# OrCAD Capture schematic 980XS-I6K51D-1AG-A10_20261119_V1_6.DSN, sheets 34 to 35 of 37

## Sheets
34 P0042_S4_USB/AUD/FLASH/XTAL: size A1
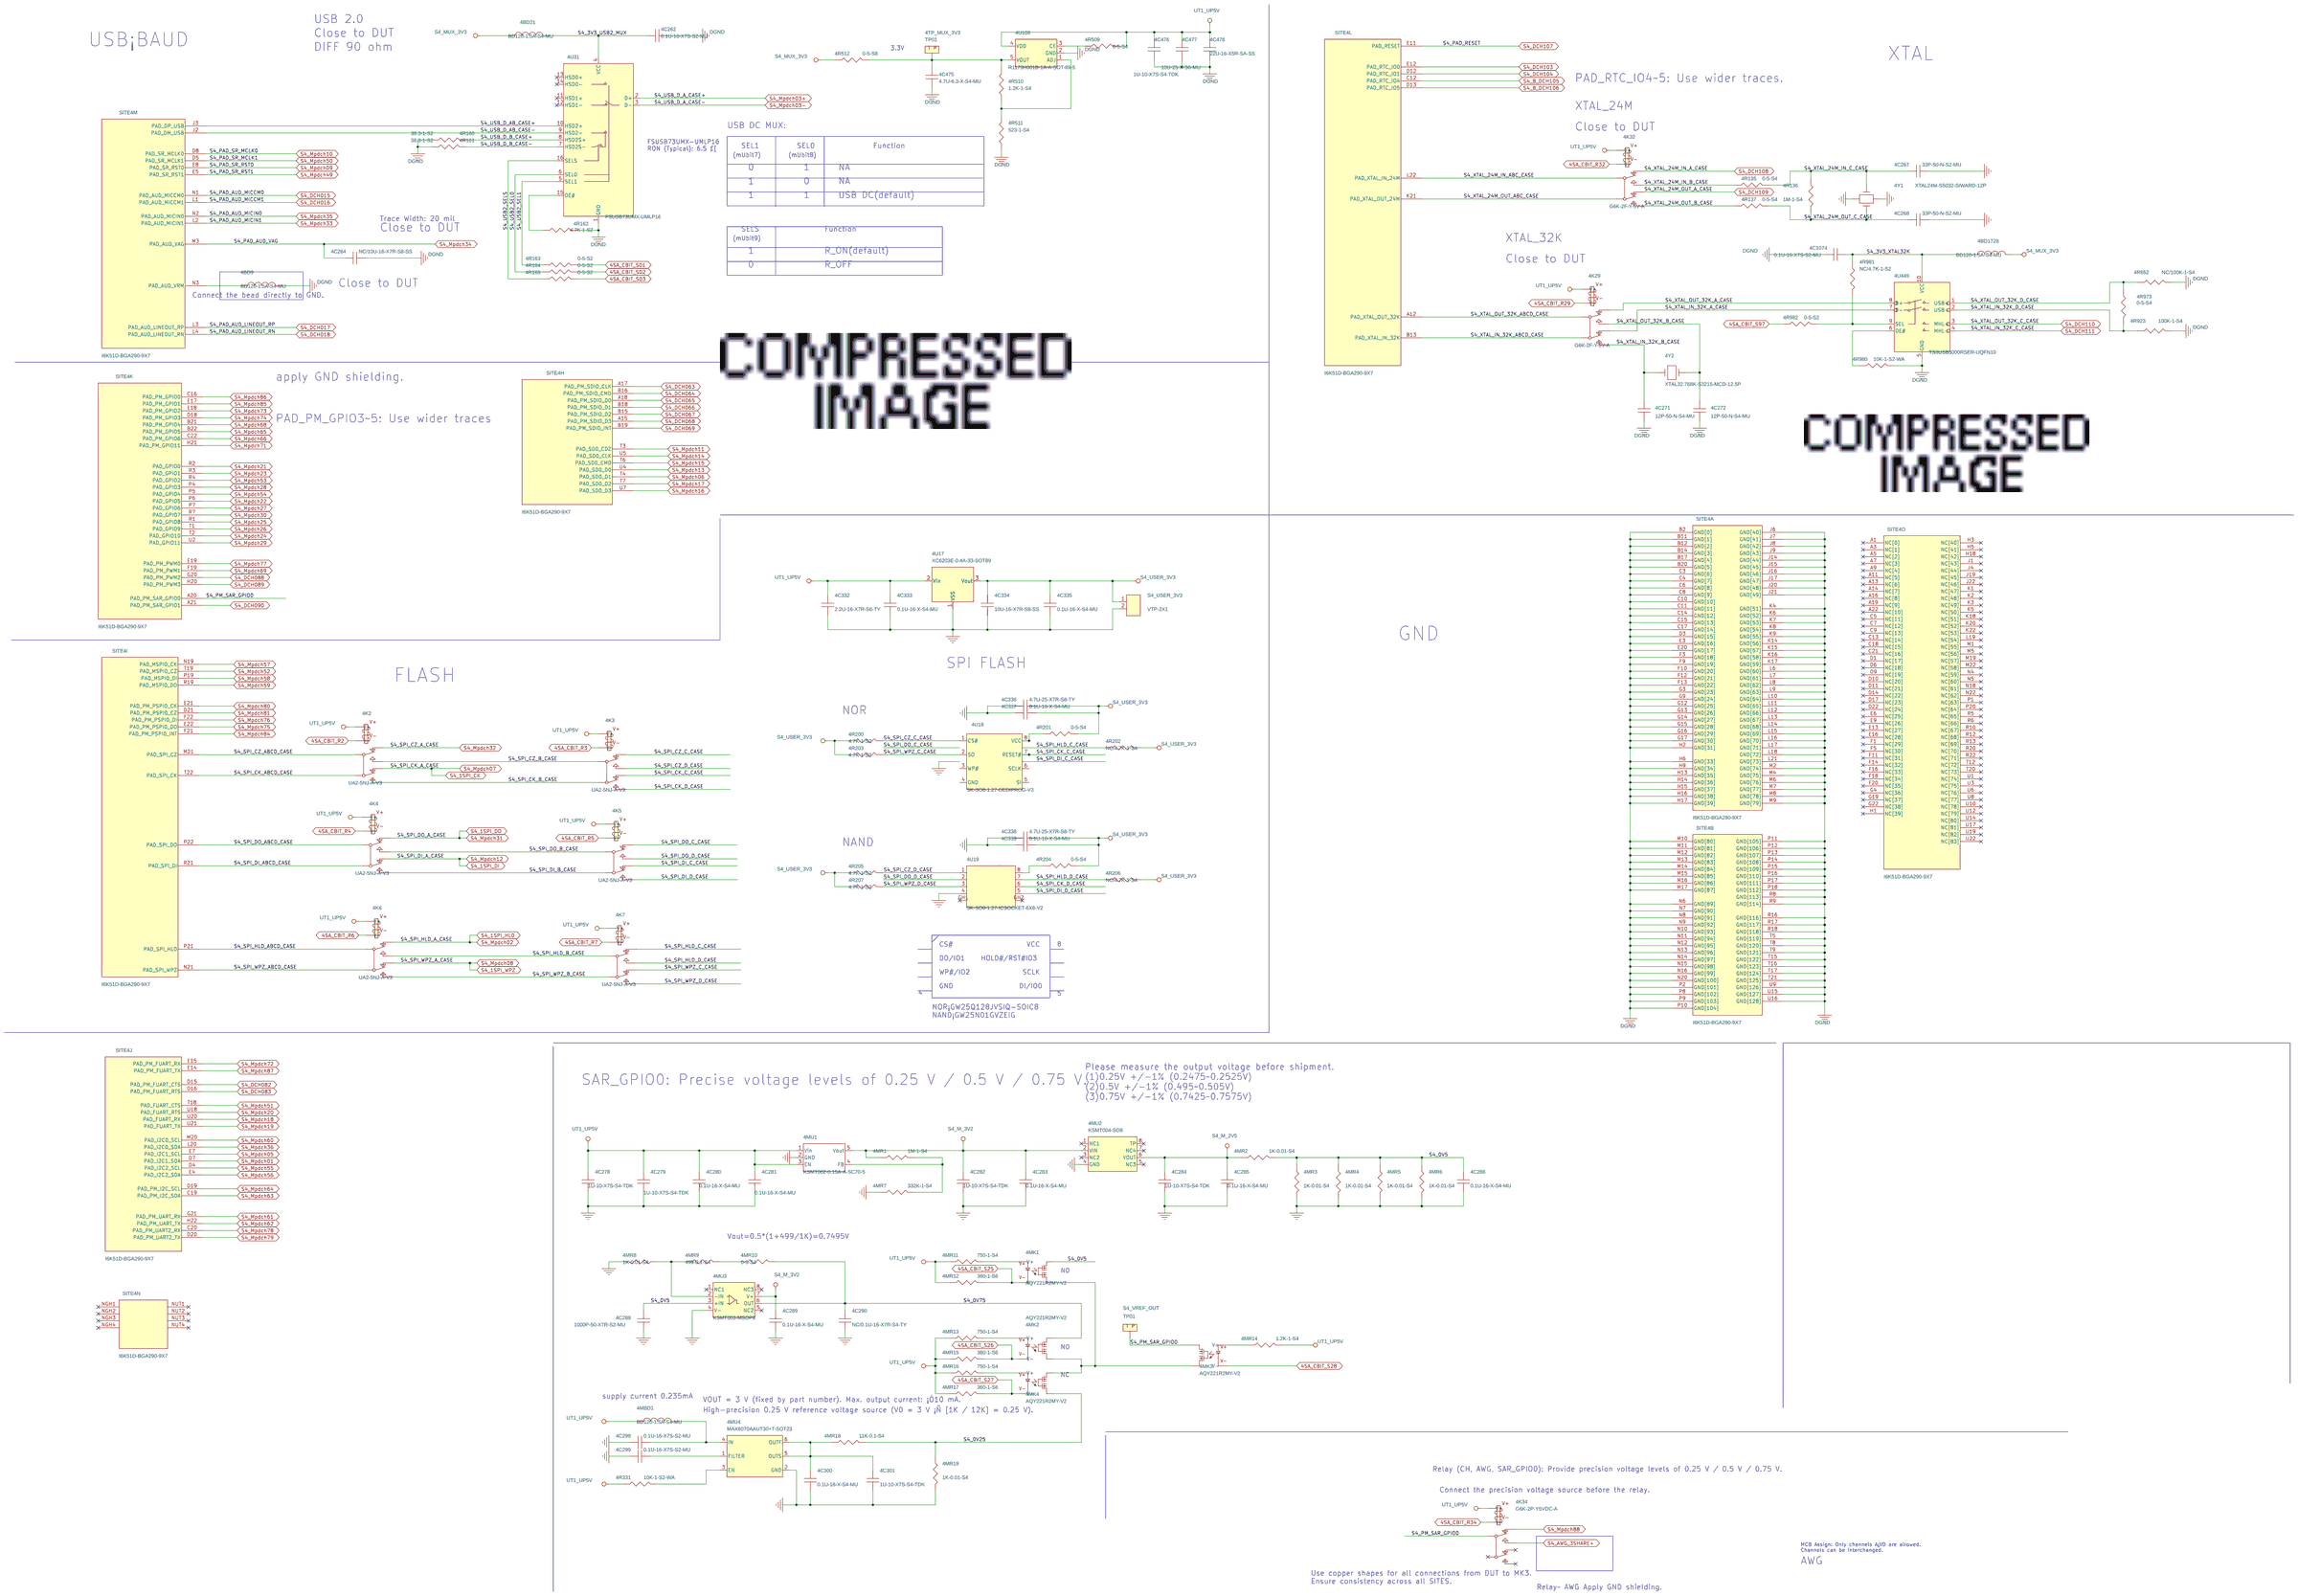
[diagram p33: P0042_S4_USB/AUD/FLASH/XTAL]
35 P0072_S7_USB/AUD/FLASH/XTAL: size A1
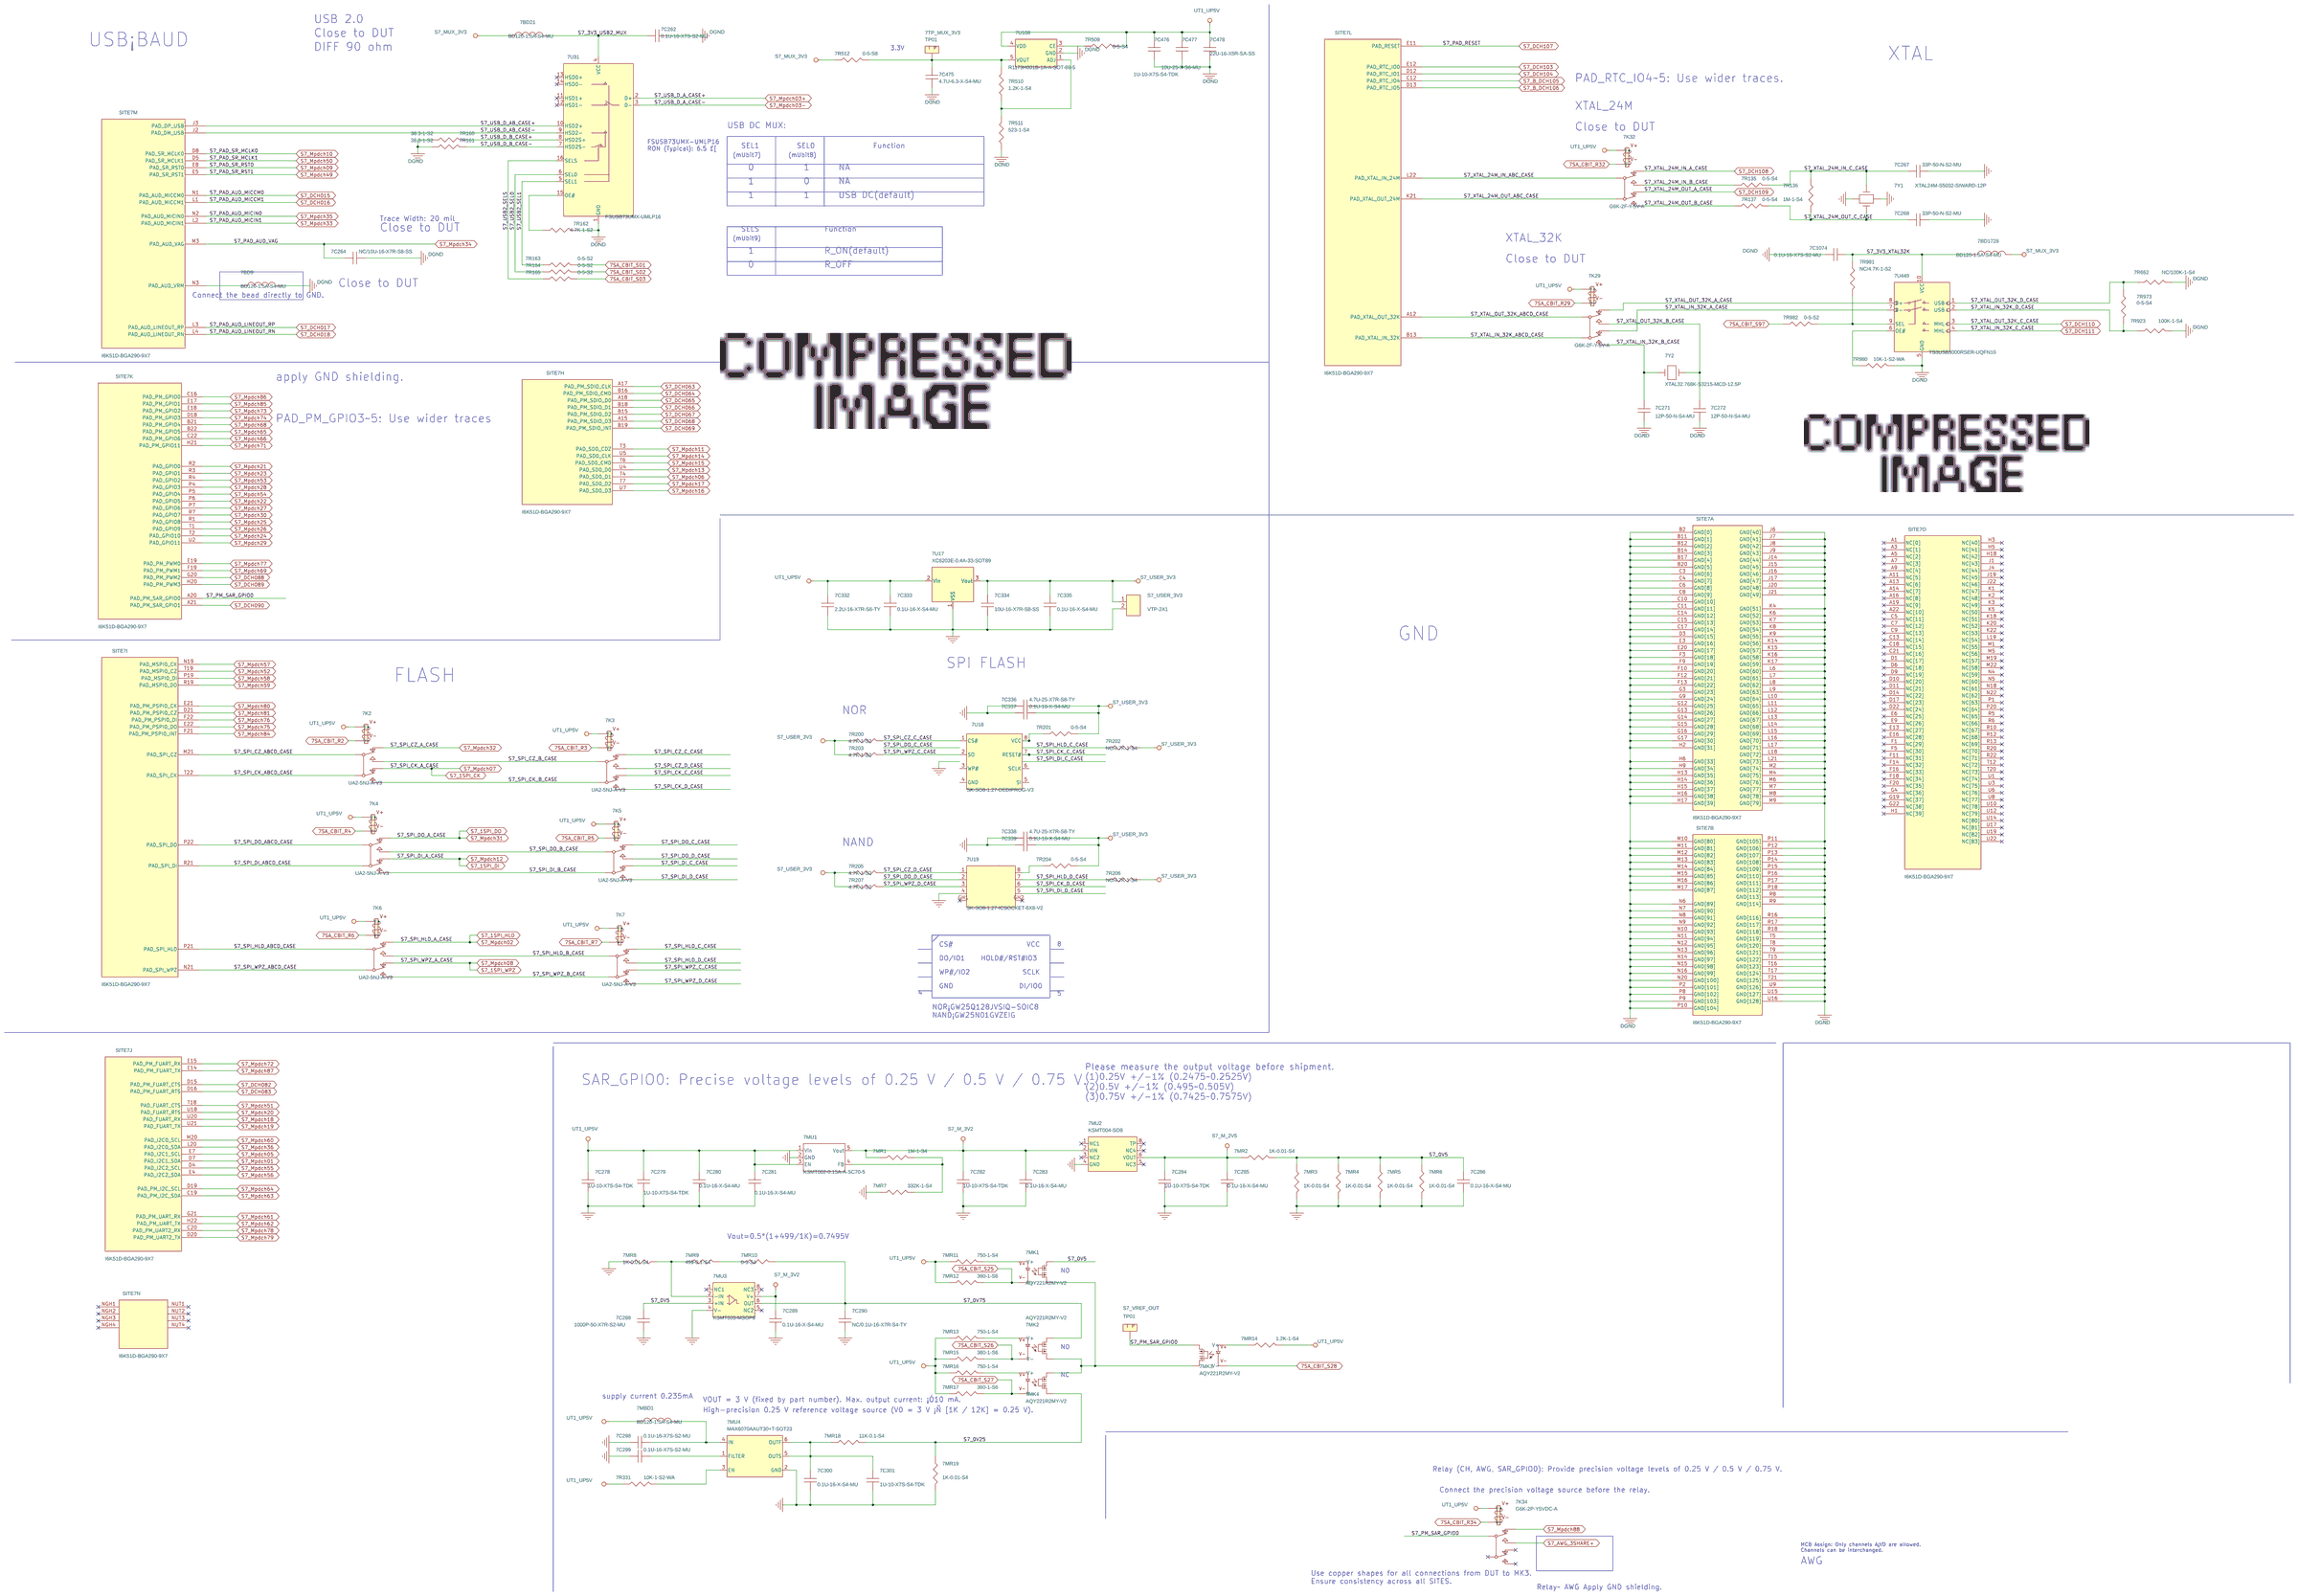
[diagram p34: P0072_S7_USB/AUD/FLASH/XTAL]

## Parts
sheet P0041_S4_POWER
SITE4  I6K51D-BGA290-9X7  [SK_TFBGA7X9_290P_0P4MM_JG]  (sections A,B,C,D,E,F,G,H,I,J,K,L,M,N,O)
sheet P0042_S4_USB/AUD/FLASH/XTAL
4BD9  BD120-1.5A-S4-MU  [FB0402]
4BD21  BD120-1.5A-S4-MU  [FB0402]
4BD1728  BD120-1.5A-S4-MU  [FB0402]
4C262  0.1U-16-X7S-S2-MU  [C0201]
4C264  NC/10U-16-X7R-S8-SS  [C0805]
4C267  33P-50-N-S2-MU  [C0201]
4C268  33P-50-N-S2-MU  [C0201]
4C271  12P-50-N-S4-MU  [C0402]
4C272  12P-50-N-S4-MU  [C0402]
4C278  1U-10-X7S-S4-TDK  [C0402]
4C279  1U-10-X7S-S4-TDK  [C0402]
4C280  0.1U-16-X-S4-MU  [C0402]
4C281  0.1U-16-X-S4-MU  [C0402]
4C282  1U-10-X7S-S4-TDK  [C0402]
4C283  0.1U-16-X-S4-MU  [C0402]
4C284  1U-10-X7S-S4-TDK  [C0402]
4C285  0.1U-16-X-S4-MU  [C0402]
4C286  0.1U-16-X-S4-MU  [C0402]
4C288  1000P-50-X7R-S2-MU  [C0201]
4C289  0.1U-16-X-S4-MU  [C0402]
4C290  NC/0.1U-16-X7R-S4-TY  [C0402]
4C298  0.1U-16-X7S-S2-MU  [C0201]
4C299  0.1U-16-X7S-S2-MU  [C0201]
4C300  0.1U-16-X-S4-MU  [C0402]
4C301  1U-10-X7S-S4-TDK  [C0402]
4C332  2.2U-16-X7R-S6-TY  [C0603]
4C333  0.1U-16-X-S4-MU  [C0402]
4C334  10U-16-X7R-S8-SS  [C0805]
4C335  0.1U-16-X-S4-MU  [C0402]
4C336  4.7U-25-X7R-S8-TY  [C0805]
4C337  0.1U-16-X-S4-MU  [C0402]
4C338  4.7U-25-X7R-S8-TY  [C0805]
4C339  0.1U-16-X-S4-MU  [C0402]
4C475  4.7U-6.3-X-S4-MU  [C0402]
4C476  1U-10-X7S-S4-TDK  [C0402]
4C477  10U-25-X-S6-MU  [C0603]
4C478  22U-16-X5R-SA-SS  [C1206]
4C1074  0.1U-16-X7S-S2-MU  [C0201_MINI]
4K2  UA2-5NJ-A-V3  [RL_NECUA2_5V_V3]
4K3  UA2-5NJ-A-V3  [RL_NECUA2_5V_V3]
4K4  UA2-5NJ-A-V3  [RL_NECUA2_5V_V3]
4K5  UA2-5NJ-A-V3  [RL_NECUA2_5V_V3]
4K6  UA2-5NJ-A-V3  [RL_NECUA2_5V_V3]
4K7  UA2-5NJ-A-V3  [RL_NECUA2_5V_V3]
4K29  G6K-2F-Y-5V-A  [RL_G6K2F-Y_5V_OMRON]
4K32  G6K-2F-Y-5V-A  [RL_G6K2F-Y_5V_OMRON]
4K34  G6K-2P-Y5VDC-A  [RL_OMRONG6K2PY_5V]
4MBD1  BD120-1.5A-S4-MU  [FB0402]
4MK1  AQY221R2MY-V2  [RL_AQY221R2MY_5V_V2]
4MK2  AQY221R2MY-V2  [RL_AQY221R2MY_5V_V2]
4MK3  AQY221R2MY-V2  [RL_AQY221R2MY_5V_V2]
4MK4  AQY221R2MY-V2  [RL_AQY221R2MY_5V_V2]
4MR1  1M-1-S4  [R0402_UNBGA_V2]
4MR2  1K-0.01-S4  [R0402_UNBGA_V2]
4MR3  1K-0.01-S4  [R0402_UNBGA_V2]
4MR4  1K-0.01-S4  [R0402_UNBGA_V2]
4MR5  1K-0.01-S4  [R0402_UNBGA_V2]
4MR6  1K-0.01-S4  [R0402_UNBGA_V2]
4MR7  332K-1-S4  [R0402_UNBGA_V2]
4MR8  1K-0.01-S4  [R0402_UNBGA_V2]
4MR9  499-0.1-S4  [R0402]
4MR10  0-5-S4  [R0402]
4MR11  750-1-S4  [R0402]
4MR12  360-1-S6  [R0603]
4MR13  750-1-S4  [R0402]
4MR14  1.2K-1-S4  [R0402]
4MR15  360-1-S6  [R0603]
4MR16  750-1-S4  [R0402]
4MR17  360-1-S6  [R0603]
4MR18  11K-0.1-S4  [R0402]
4MR19  1K-0.01-S4  [R0402_UNBGA_V2]
4MU1  KSMT002-0.15A-A-SC70-5  [SC70_5P]
4MU2  KSMT004-SO8  [SO8_244X127MM]
4MU3  KSMT003-MSOP8  [SO8_172X0P65MM]
4MU4  MAX6070AAUT30+T-SOT23  [SOT23_6P_0P95X2P7MM_H1P45MM]
4R135  0-5-S4  [R0402]
4R136  1M-1-S4  [R0402]
4R137  0-5-S4  [R0402]
4R160  38.3-1-S2  [R0201_MINI]
4R161  38.3-1-S2  [R0201_MINI]
4R162  4.7K-1-S2  [R0201_MINI]
4R163  0-5-S2  [R0201_MINI]
4R164  0-5-S2  [R0201_MINI]
4R165  0-5-S2  [R0201_MINI]
4R200  4.7K-1-S2  [R0201]
4R201  0-5-S4  [R0402]
4R202  NC/4.7K-1-S4  [R0402]
4R203  4.7K-1-S2  [R0201]
4R204  0-5-S4  [R0402]
4R205  4.7K-1-S2  [R0201]
4R206  NC/4.7K-1-S4  [R0402]
4R207  4.7K-1-S2  [R0201]
4R331  10K-1-S2-WA  [R0201]
4R509  0-5-S4  [R0402]
4R510  1.2K-1-S4  [R0402]
4R511  523-1-S4  [R0402]
4R512  0-5-S8  [R0805]
4R652  NC/100K-1-S4  [R0402]
4R923  100K-1-S4  [R0402]
4R973  0-5-S4  [R0402]
4R980  10K-1-S2-WA  [R0201]
4R981  NC/4.7K-1-S2  [R0201]
4R982  0-5-S2  [R0201]
4TP_MUX_3V3  TP01  [TP_040_T]
4U17  XC6203E-0.4A-33-SOT89  [SOT89]
4U18  SK-SO8-1.27-DEDIPROG-V3  [SK_SO8_1P27MM_DEDIPROG_V3]
4U19  SK-SO8-1.27-ICSOCKET-6X8-V2  [SK_SO8_1P27MM_SDQ54CBAA_V2]
4U31  FSUSB73UMX-UMLP16  [SW_UMLP2P6X1P8_12P_0P4MM]
4U108  R1173H001B-1A-A-SOT-89-5  [SOT_89_5]
4U449  TS3USB3000RSER-UQFN10  [UQFN2P05X1P55_10P_0P5MM]
4Y1  XTAL24M-S5032-SIWARD-12P  [XTAL_S_DUAL1]
4Y2  XTAL32.768K-S3215-MCD-12.5P  [XTAL_3P2X1P5MM_2P_MC]
S4_USER_3V3  VTP-2X1  [VTP_2P_100]
S4_VREF_OUT  TP01  [TP_040_T]
sheet P0072_S7_USB/AUD/FLASH/XTAL
7BD9  BD120-1.5A-S4-MU  [FB0402]
7BD21  BD120-1.5A-S4-MU  [FB0402]
7BD1728  BD120-1.5A-S4-MU  [FB0402]
7C262  0.1U-16-X7S-S2-MU  [C0201]
7C264  NC/10U-16-X7R-S8-SS  [C0805]
7C267  33P-50-N-S2-MU  [C0201]
7C268  33P-50-N-S2-MU  [C0201]
7C271  12P-50-N-S4-MU  [C0402]
7C272  12P-50-N-S4-MU  [C0402]
7C278  1U-10-X7S-S4-TDK  [C0402]
7C279  1U-10-X7S-S4-TDK  [C0402]
7C280  0.1U-16-X-S4-MU  [C0402]
7C281  0.1U-16-X-S4-MU  [C0402]
7C282  1U-10-X7S-S4-TDK  [C0402]
7C283  0.1U-16-X-S4-MU  [C0402]
7C284  1U-10-X7S-S4-TDK  [C0402]
7C285  0.1U-16-X-S4-MU  [C0402]
7C286  0.1U-16-X-S4-MU  [C0402]
7C288  1000P-50-X7R-S2-MU  [C0201]
7C289  0.1U-16-X-S4-MU  [C0402]
7C290  NC/0.1U-16-X7R-S4-TY  [C0402]
7C298  0.1U-16-X7S-S2-MU  [C0201]
7C299  0.1U-16-X7S-S2-MU  [C0201]
7C300  0.1U-16-X-S4-MU  [C0402]
7C301  1U-10-X7S-S4-TDK  [C0402]
7C332  2.2U-16-X7R-S6-TY  [C0603]
7C333  0.1U-16-X-S4-MU  [C0402]
7C334  10U-16-X7R-S8-SS  [C0805]
7C335  0.1U-16-X-S4-MU  [C0402]
7C336  4.7U-25-X7R-S8-TY  [C0805]
7C337  0.1U-16-X-S4-MU  [C0402]
7C338  4.7U-25-X7R-S8-TY  [C0805]
7C339  0.1U-16-X-S4-MU  [C0402]
7C475  4.7U-6.3-X-S4-MU  [C0402]
7C476  1U-10-X7S-S4-TDK  [C0402]
7C477  10U-25-X-S6-MU  [C0603]
7C478  22U-16-X5R-SA-SS  [C1206]
7C1074  0.1U-16-X7S-S2-MU  [C0201_MINI]
7K2  UA2-5NJ-A-V3  [RL_NECUA2_5V_V3]
7K3  UA2-5NJ-A-V3  [RL_NECUA2_5V_V3]
7K4  UA2-5NJ-A-V3  [RL_NECUA2_5V_V3]
7K5  UA2-5NJ-A-V3  [RL_NECUA2_5V_V3]
7K6  UA2-5NJ-A-V3  [RL_NECUA2_5V_V3]
7K7  UA2-5NJ-A-V3  [RL_NECUA2_5V_V3]
7K29  G6K-2F-Y-5V-A  [RL_G6K2F-Y_5V_OMRON]
7K32  G6K-2F-Y-5V-A  [RL_G6K2F-Y_5V_OMRON]
7K34  G6K-2P-Y5VDC-A  [RL_OMRONG6K2PY_5V]
7MBD1  BD120-1.5A-S4-MU  [FB0402]
7MK1  AQY221R2MY-V2  [RL_AQY221R2MY_5V_V2]
7MK2  AQY221R2MY-V2  [RL_AQY221R2MY_5V_V2]
7MK3  AQY221R2MY-V2  [RL_AQY221R2MY_5V_V2]
7MK4  AQY221R2MY-V2  [RL_AQY221R2MY_5V_V2]
7MR1  1M-1-S4  [R0402_UNBGA_V2]
7MR2  1K-0.01-S4  [R0402_UNBGA_V2]
7MR3  1K-0.01-S4  [R0402_UNBGA_V2]
7MR4  1K-0.01-S4  [R0402_UNBGA_V2]
7MR5  1K-0.01-S4  [R0402_UNBGA_V2]
7MR6  1K-0.01-S4  [R0402_UNBGA_V2]
7MR7  332K-1-S4  [R0402_UNBGA_V2]
7MR8  1K-0.01-S4  [R0402_UNBGA_V2]
7MR9  499-0.1-S4  [R0402]
7MR10  0-5-S4  [R0402]
7MR11  750-1-S4  [R0402]
7MR12  360-1-S6  [R0603]
7MR13  750-1-S4  [R0402]
7MR14  1.2K-1-S4  [R0402]
7MR15  360-1-S6  [R0603]
7MR16  750-1-S4  [R0402]
7MR17  360-1-S6  [R0603]
7MR18  11K-0.1-S4  [R0402]
7MR19  1K-0.01-S4  [R0402_UNBGA_V2]
7MU1  KSMT002-0.15A-A-SC70-5  [SC70_5P]
7MU2  KSMT004-SO8  [SO8_244X127MM]
7MU3  KSMT003-MSOP8  [SO8_172X0P65MM]
7MU4  MAX6070AAUT30+T-SOT23  [SOT23_6P_0P95X2P7MM_H1P45MM]
7R135  0-5-S4  [R0402]
7R136  1M-1-S4  [R0402]
7R137  0-5-S4  [R0402]
7R160  38.3-1-S2  [R0201_MINI]
7R161  38.3-1-S2  [R0201_MINI]
7R162  4.7K-1-S2  [R0201_MINI]
7R163  0-5-S2  [R0201_MINI]
7R164  0-5-S2  [R0201_MINI]
7R165  0-5-S2  [R0201_MINI]
7R200  4.7K-1-S2  [R0201]
7R201  0-5-S4  [R0402]
7R202  NC/4.7K-1-S4  [R0402]
7R203  4.7K-1-S2  [R0201]
7R204  0-5-S4  [R0402]
7R205  4.7K-1-S2  [R0201]
7R206  NC/4.7K-1-S4  [R0402]
7R207  4.7K-1-S2  [R0201]
7R331  10K-1-S2-WA  [R0201]
7R509  0-5-S4  [R0402]
7R510  1.2K-1-S4  [R0402]
7R511  523-1-S4  [R0402]
7R512  0-5-S8  [R0805]
7R652  NC/100K-1-S4  [R0402]
7R923  100K-1-S4  [R0402]
7R973  0-5-S4  [R0402]
7R980  10K-1-S2-WA  [R0201]
7R981  NC/4.7K-1-S2  [R0201]
7R982  0-5-S2  [R0201]
7TP_MUX_3V3  TP01  [TP_040_T]
7U17  XC6203E-0.4A-33-SOT89  [SOT89]
7U18  SK-SO8-1.27-DEDIPROG-V3  [SK_SO8_1P27MM_DEDIPROG_V3]
7U19  SK-SO8-1.27-ICSOCKET-6X8-V2  [SK_SO8_1P27MM_SDQ54CBAA_V2]
7U31  FSUSB73UMX-UMLP16  [SW_UMLP2P6X1P8_12P_0P4MM]
7U108  R1173H001B-1A-A-SOT-89-5  [SOT_89_5]
7U449  TS3USB3000RSER-UQFN10  [UQFN2P05X1P55_10P_0P5MM]
7Y1  XTAL24M-S5032-SIWARD-12P  [XTAL_S_DUAL1]
7Y2  XTAL32.768K-S3215-MCD-12.5P  [XTAL_3P2X1P5MM_2P_MC]
S7_USER_3V3  VTP-2X1  [VTP_2P_100]
S7_VREF_OUT  TP01  [TP_040_T]
SITE7  I6K51D-BGA290-9X7  [SK_TFBGA7X9_290P_0P4MM_JG]  (sections A,B,C,D,E,F,G,H,I,J,K,L,M,N,O)

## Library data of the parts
SITE4 SITE7 = I6K51D-BGA290-9X7
4BD9 7BD9 = BD120-1.5A-S4-MU: KAIROSNAME: BD9
4BD21 4BD1728 7BD21 7BD1728 = BD120-1.5A-S4-MU: KAIROSNAME: BD21
4C262 7C262 = 0.1U-16-X7S-S2-MU
4C264 7C264 = 10U-16-X7R-S8-SS: KAIROSNAME: C264
4C267 7C267 = 33P-50-N-S2-MU: KAIROSNAME: C267
4C268 7C268 = 33P-50-N-S2-MU: KAIROSNAME: C268
4C271 7C271 = 12P-50-N-S4-MU: KAIROSNAME: C271
4C272 7C272 = 12P-50-N-S4-MU: KAIROSNAME: C272
4C278 7C278 = 1U-10-X7S-S4-TDK: KAIROSNAME: C278
4C279 7C279 = 1U-10-X7S-S4-TDK: KAIROSNAME: C279
4C280 7C280 = 0.1U-16-X-S4-MU: KAIROSNAME: C280
4C281 7C281 = 0.1U-16-X-S4-MU: KAIROSNAME: C281
4C282 7C282 = 1U-10-X7S-S4-TDK: KAIROSNAME: C282
4C283 7C283 = 0.1U-16-X-S4-MU: KAIROSNAME: C283
4C284 7C284 = 1U-10-X7S-S4-TDK: KAIROSNAME: C284
4C285 7C285 = 0.1U-16-X-S4-MU: KAIROSNAME: C285
4C286 7C286 = 0.1U-16-X-S4-MU: KAIROSNAME: C286
4C288 7C288 = 1000P-50-X7R-S2-MU: KAIROSNAME: C288
4C289 7C289 = 0.1U-16-X-S4-MU: KAIROSNAME: C289
4C290 7C290 = 0.1U-16-X-S4-MU: KAIROSNAME: C290
4C298 7C298 = 0.1U-16-X7S-S2-MU: KAIROSNAME: C298
4C299 7C299 = 0.1U-16-X7S-S2-MU: KAIROSNAME: C299
4C300 7C300 = 0.1U-16-X-S4-MU: KAIROSNAME: C300
4C301 7C301 = 1U-10-X7S-S4-TDK: KAIROSNAME: C301
4C332 7C332 = 2.2U-16-X7R-S6-TY
4C333 4C335 4C337 4C339 7C333 7C335 7C337 7C339 = 0.1U-16-X-S4-MU
4C334 7C334 = 10U-16-X7R-S8-SS
4C336 4C338 7C336 7C338 = 4.7U-25-X7R-S8-TY
4C475 7C475 = 4.7U-6.3-X-S4-MU: KAIROSNAME: C475
4C476 7C476 = 1U-10-X-S4-MU: KAIROSNAME: C476
4C477 7C477 = 10U-25-X-S6-MU: KAIROSNAME: C477
4C478 7C478 = 22U-16-X5R-SA-SS: KAIROSNAME: C478
4C1074 7C1074 = 0.1U-16-X7S-S2-MU: KAIROSNAME: C262
4K2-4K7 7K2-7K7 = UA2-5NJ-A-V3
4K29 7K29 = G6K-2F-Y-5V-A: KAIROSNAME: K29
4K32 7K32 = G6K-2F-Y-5V-A: KAIROSNAME: K32
4K34 7K34 = G6K-2P-Y5VDC-A: KAIROSNAME: K34
4MBD1 7MBD1 = BD120-1.5A-S4-MU: KAIROSNAME: MBD1
4MK1 7MK1 = AQY221R2MY-V2: KAIROSNAME: MK1
4MK2 7MK2 = AQY221R2MY-V2: KAIROSNAME: MK2
4MK3 7MK3 = AQY221R2MY-V2: KAIROSNAME: MK3
4MK4 7MK4 = AQY221R2MY-V2: KAIROSNAME: MK4
4MR1 7MR1 = 1M-1-S4: KAIROSNAME: MR1
4MR2 7MR2 = 1K-0.01-S4: KAIROSNAME: MR2
4MR3 7MR3 = 1K-0.01-S4: KAIROSNAME: MR3
4MR4 7MR4 = 1K-0.01-S4: KAIROSNAME: MR4
4MR5 7MR5 = 1K-0.01-S4: KAIROSNAME: MR5
4MR6 7MR6 = 1K-0.01-S4: KAIROSNAME: MR6
4MR7 7MR7 = 332K-1-S4: KAIROSNAME: MR7
4MR8 7MR8 = 1K-0.01-S4: KAIROSNAME: MR8
4MR9 7MR9 = 499-0.1-S4: KAIROSNAME: MR9
4MR10 7MR10 = 0-5-S4: KAIROSNAME: MR10
4MR11 7MR11 = 750-1-S4: KAIROSNAME: MR11
4MR12 7MR12 = 360-1-S4: KAIROSNAME: MR12
4MR13 7MR13 = 750-1-S4: KAIROSNAME: MR13
4MR14 7MR14 = 1.2K-1-S4: KAIROSNAME: MR14
4MR15 7MR15 = 360-1-S4: KAIROSNAME: MR15
4MR16 7MR16 = 750-1-S4: KAIROSNAME: MR16
4MR17 7MR17 = 360-1-S4: KAIROSNAME: MR17
4MR18 7MR18 = 11K-0.1-S4: KAIROSNAME: MR18
4MR19 7MR19 = 1K-0.01-S4: KAIROSNAME: MR19
4MU1 7MU1 = KSMT002-0.15A-A-SC70-5: KAIROSNAME: MU1
4MU2 7MU2 = KSMT004-SO8: KAIROSNAME: MU2
4MU3 7MU3 = KSMT003-MSOP8: KAIROSNAME: MU3
4MU4 7MU4 = MAX6070AAUT30+T-SOT23: KAIROSNAME: MU4
4R135 7R135 = 0-5-S4: KAIROSNAME: R135
4R136 7R136 = 1M-1-S4: KAIROSNAME: R136
4R137 7R137 = 0-5-S4: KAIROSNAME: R137
4R160 7R160 = 38.3-1-S2: KAIROSNAME: R160
4R161 7R161 = 38.3-1-S2: KAIROSNAME: R161
4R162 7R162 = 4.7K-1-S2: KAIROSNAME: R162
4R163 7R163 = 0-5-S2: KAIROSNAME: R163
4R164 7R164 = 0-5-S2: KAIROSNAME: R164
4R165 7R165 = 0-5-S2: KAIROSNAME: R165
4R200 4R202 4R203 4R205-4R207 4R981 7R200 7R202 7R203 7R205-7R207 7R981 = 4.7K-1-S2
4R201 4R204 4R973 7R201 7R204 7R973 = 0-5-S4
4R331 7R331 = 10K-1-S2-WA: KAIROSNAME: R331
4R509 7R509 = 0-5-S4: KAIROSNAME: R509
4R510 7R510 = 1.2K-1-S4: KAIROSNAME: R510
4R511 7R511 = 523-1-S4: KAIROSNAME: R511
4R512 7R512 = 0-5-S8: KAIROSNAME: R512
4R652 4R923 7R652 7R923 = 100K-1-S4
4R980 7R980 = 10K-1-S2-WA
4R982 7R982 = 0-5-S2
4TP_MUX_3V3 7TP_MUX_3V3 = TP03-D: KAIROSNAME: TP_MUX_3V3
4U17 7U17 = XC6203E-0.4A-33-SOT89
4U18 7U18 = SK-SO8-1.27-DEDIPROG-V3
4U19 7U19 = SK-SO8-1.27-ICSOCKET-6X8-V2
4U31 7U31 = FSUSB73UMX-UMLP16: KAIROSNAME: U31
4U108 7U108 = R1173H001B-1A-A-SOT-89-5: KAIROSNAME: U108
4U449 7U449 = TS3USB3000RSER-UQFN10
4Y1 7Y1 = XTAL24M-S5032-SIWARD-12P: KAIROSNAME: Y1
4Y2 7Y2 = XTAL32.768K-S3215-MCD-12.5P: KAIROSNAME: Y2
S4_USER_3V3 S7_USER_3V3 = VTP-2X1
S4_VREF_OUT S7_VREF_OUT = TP01: KAIROSNAME: S1_VREF_OUT

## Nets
DGND: 4BD9.2 4C262.2 4C264.2 4C267.2 4C268.2 4C271.2 4C272.2 4C278.2 4C279.2 4C280.2 4C281.2 4C282.2 4C283.2 4C284.2 4C285.2 4C286.2 4C288.2 4C289.2 4C290.2 4C298.1 4C299.1 4C300.2 4C301.2 4C332.2 4C333.2 4C334.2 4C335.2 4C336.1 4C337.1 4C338.1 4C339.1 4C475.2 4C476.2 4C477.2 4C478.2 4C1074.2 4MR3.2 4MR4.2 4MR5.2 4MR6.2 4MR7.1 4MR8.2 4MR19.2 4MU1.2(GND) 4MU2.4(GND) 4MU3.4(V-) 4MU4.2(GND) 4R160.1 4R161.1 4R162.2 4R511.2 4R652.2 4R923.2 4R980.2 4U17.1(VSS) 4U19.4 4U31.1(GND) 4U108.2(GND) 4U449.5(GND) 4Y1.2 4Y1.4 7BD9.2 7C262.2 7C264.2 7C267.2 7C268.2 7C271.2 7C272.2 7C278.2 7C279.2 7C280.2 7C281.2 7C282.2 7C283.2 7C284.2 7C285.2 7C286.2 7C288.2 7C289.2 7C290.2 7C298.1 7C299.1 7C300.2 7C301.2 7C332.2 7C333.2 7C334.2 7C335.2 7C336.1 7C337.1 7C338.1 7C339.1 7C475.2 7C476.2 7C477.2 7C478.2 7C1074.2 7MR3.2 7MR4.2 7MR5.2 7MR6.2 7MR7.1 7MR8.2 7MR19.2 7MU1.2(GND) 7MU2.4(GND) 7MU3.4(V-) 7MU4.2(GND) 7R160.1 7R161.1 7R162.2 7R511.2 7R652.2 7R923.2 7R980.2 7U17.1(VSS) 7U19.4 7U31.1(GND) 7U108.2(GND) 7U449.5(GND) 7Y1.2 7Y1.4 S4_USER_3V3.2 S7_USER_3V3.2 SITE4.B2(GND[0]) SITE4.B11(GND[1]) SITE4.B12(GND[2]) SITE4.B14(GND[3]) SITE4.B17(GND[4]) SITE4.B20(GND[5]) SITE4.C3(GND[6]) SITE4.C4(GND[7]) SITE4.C6(GND[8]) SITE4.C8(GND[9]) SITE4.C10(GND[10]) SITE4.C11(GND[11]) SITE4.C14(GND[12]) SITE4.C15(GND[13]) SITE4.C17(GND[14]) SITE4.D3(GND[15]) SITE4.E3(GND[16]) SITE4.E20(GND[17]) SITE4.F3(GND[18]) SITE4.F9(GND[19]) SITE4.F10(GND[20]) SITE4.F12(GND[21]) SITE4.F13(GND[22]) SITE4.G3(GND[23]) SITE4.G9(GND[24]) SITE4.G12(GND[25]) SITE4.G13(GND[26]) SITE4.G14(GND[27]) SITE4.G15(GND[28]) SITE4.G16(GND[29]) SITE4.G17(GND[30]) SITE4.H2(GND[31]) SITE4.H6(GND[33]) SITE4.H9(GND[34]) SITE4.H13(GND[35]) SITE4.H14(GND[36]) SITE4.H15(GND[37]) SITE4.H16(GND[38]) SITE4.H17(GND[39]) SITE4.J6(GND[40]) SITE4.J7(GND[41]) SITE4.J8(GND[42]) SITE4.J9(GND[43]) SITE4.J14(GND[44]) SITE4.J15(GND[45]) SITE4.J16(GND[46]) SITE4.J17(GND[47]) SITE4.J20(GND[48]) SITE4.J21(GND[49]) SITE4.K4(GND[51]) SITE4.K6(GND[52]) SITE4.K7(GND[53]) SITE4.K8(GND[54]) SITE4.K9(GND[55]) SITE4.K14(GND[56]) SITE4.K15(GND[57]) SITE4.K16(GND[58]) SITE4.K17(GND[59]) SITE4.L6(GND[60]) SITE4.L7(GND[61]) SITE4.L8(GND[62]) SITE4.L9(GND[63]) SITE4.L10(GND[64]) SITE4.L11(GND[65]) SITE4.L12(GND[66]) SITE4.L13(GND[67]) SITE4.L14(GND[68]) SITE4.L15(GND[69]) SITE4.L16(GND[70]) SITE4.L17(GND[71]) SITE4.L18(GND[72]) SITE4.L21(GND[73]) SITE4.M2(GND[74]) SITE4.M4(GND[75]) SITE4.M6(GND[76]) SITE4.M7(GND[77]) SITE4.M8(GND[78]) SITE4.M9(GND[79]) SITE4.M10(GND[80]) SITE4.M11(GND[81]) SITE4.M12(GND[82]) SITE4.M13(GND[83]) SITE4.M14(GND[84]) SITE4.M15(GND[85]) SITE4.M16(GND[86]) SITE4.M17(GND[87]) SITE4.N6(GND[89]) SITE4.N7(GND[90]) SITE4.N8(GND[91]) SITE4.N9(GND[92]) SITE4.N10(GND[93]) SITE4.N11(GND[94]) SITE4.N12(GND[95]) SITE4.N13(GND[96]) SITE4.N14(GND[97]) SITE4.N15(GND[98]) SITE4.N16(GND[99]) SITE4.N20(GND[100]) SITE4.P2(GND[101]) SITE4.P8(GND[102]) SITE4.P9(GND[103]) SITE4.P10(GND[104]) SITE4.P11(GND[105]) SITE4.P12(GND[106]) SITE4.P13(GND[107]) SITE4.P14(GND[108]) SITE4.P15(GND[109]) SITE4.P16(GND[110]) SITE4.P17(GND[111]) SITE4.P18(GND[112]) SITE4.R8(GND[113]) SITE4.R9(GND[114]) SITE4.R16(GND[116]) SITE4.R17(GND[117]) SITE4.R18(GND[118]) SITE4.T5(GND[119]) SITE4.T8(GND[120]) SITE4.T9(GND[121]) SITE4.T15(GND[122]) SITE4.T16(GND[123]) SITE4.T17(GND[124]) SITE4.T21(GND[125]) SITE4.U9(GND[126]) SITE4.U15(GND[127]) SITE4.U16(GND[128]) SITE7.B2(GND[0]) SITE7.B11(GND[1]) SITE7.B12(GND[2]) SITE7.B14(GND[3]) SITE7.B17(GND[4]) SITE7.B20(GND[5]) SITE7.C3(GND[6]) SITE7.C4(GND[7]) SITE7.C6(GND[8]) SITE7.C8(GND[9]) SITE7.C10(GND[10]) SITE7.C11(GND[11]) SITE7.C14(GND[12]) SITE7.C15(GND[13]) SITE7.C17(GND[14]) SITE7.D3(GND[15]) SITE7.E3(GND[16]) SITE7.E20(GND[17]) SITE7.F3(GND[18]) SITE7.F9(GND[19]) SITE7.F10(GND[20]) SITE7.F12(GND[21]) SITE7.F13(GND[22]) SITE7.G3(GND[23]) SITE7.G9(GND[24]) SITE7.G12(GND[25]) SITE7.G13(GND[26]) SITE7.G14(GND[27]) SITE7.G15(GND[28]) SITE7.G16(GND[29]) SITE7.G17(GND[30]) SITE7.H2(GND[31]) SITE7.H6(GND[33]) SITE7.H9(GND[34]) SITE7.H13(GND[35]) SITE7.H14(GND[36]) SITE7.H15(GND[37]) SITE7.H16(GND[38]) SITE7.H17(GND[39]) SITE7.J6(GND[40]) SITE7.J7(GND[41]) SITE7.J8(GND[42]) SITE7.J9(GND[43]) SITE7.J14(GND[44]) SITE7.J15(GND[45]) SITE7.J16(GND[46]) SITE7.J17(GND[47]) SITE7.J20(GND[48]) SITE7.J21(GND[49]) SITE7.K4(GND[51]) SITE7.K6(GND[52]) SITE7.K7(GND[53]) SITE7.K8(GND[54]) SITE7.K9(GND[55]) SITE7.K14(GND[56]) SITE7.K15(GND[57]) SITE7.K16(GND[58]) SITE7.K17(GND[59]) SITE7.L6(GND[60]) SITE7.L7(GND[61]) SITE7.L8(GND[62]) SITE7.L9(GND[63]) SITE7.L10(GND[64]) SITE7.L11(GND[65]) SITE7.L12(GND[66]) SITE7.L13(GND[67]) SITE7.L14(GND[68]) SITE7.L15(GND[69]) SITE7.L16(GND[70]) SITE7.L17(GND[71]) SITE7.L18(GND[72]) SITE7.L21(GND[73]) SITE7.M2(GND[74]) SITE7.M4(GND[75]) SITE7.M6(GND[76]) SITE7.M7(GND[77]) SITE7.M8(GND[78]) SITE7.M9(GND[79]) SITE7.M10(GND[80]) SITE7.M11(GND[81]) SITE7.M12(GND[82]) SITE7.M13(GND[83]) SITE7.M14(GND[84]) SITE7.M15(GND[85]) SITE7.M16(GND[86]) SITE7.M17(GND[87]) SITE7.N6(GND[89]) SITE7.N7(GND[90]) SITE7.N8(GND[91]) SITE7.N9(GND[92]) SITE7.N10(GND[93]) SITE7.N11(GND[94]) SITE7.N12(GND[95]) SITE7.N13(GND[96]) SITE7.N14(GND[97]) SITE7.N15(GND[98]) SITE7.N16(GND[99]) SITE7.N20(GND[100]) SITE7.P2(GND[101]) SITE7.P8(GND[102]) SITE7.P9(GND[103]) SITE7.P10(GND[104]) SITE7.P11(GND[105]) SITE7.P12(GND[106]) SITE7.P13(GND[107]) SITE7.P14(GND[108]) SITE7.P15(GND[109]) SITE7.P16(GND[110]) SITE7.P17(GND[111]) SITE7.P18(GND[112]) SITE7.R8(GND[113]) SITE7.R9(GND[114]) SITE7.R16(GND[116]) SITE7.R17(GND[117]) SITE7.R18(GND[118]) SITE7.T5(GND[119]) SITE7.T8(GND[120]) SITE7.T9(GND[121]) SITE7.T15(GND[122]) SITE7.T16(GND[123]) SITE7.T17(GND[124]) SITE7.T21(GND[125]) SITE7.U9(GND[126]) SITE7.U15(GND[127]) SITE7.U16(GND[128]) ; also on sheet 1 2 3 4 5 6 7 8 9 10 11 12 13 14 17 18 19 20 21 22 23 24 25 26 27 28 30 31 32 33 36 37
4SA_CBIT_R2: 4K2.8(V-)
4SA_CBIT_R3: 4K3.8(V-)
4SA_CBIT_R4: 4K4.8(V-)
4SA_CBIT_R5: 4K5.8(V-)
4SA_CBIT_R6: 4K6.8(V-)
4SA_CBIT_R7: 4K7.8(V-)
4SA_CBIT_R29: 4K29.8(V-)
4SA_CBIT_R32: 4K32.8(V-)
4SA_CBIT_R34: 4K34.8(V-)
4SA_CBIT_S01: 4R163.1
4SA_CBIT_S02: 4R164.1
4SA_CBIT_S03: 4R165.1
4SA_CBIT_S25: 4MK1.2(V-) 4MR12.2
4SA_CBIT_S26: 4MK2.2(V-) 4MR15.2
4SA_CBIT_S27: 4MK4.2(V-) 4MR17.2
4SA_CBIT_S28: 4MK3.2(V-)
4SA_CBIT_S97: 4R982.1
7SA_CBIT_R2: 7K2.8(V-)
7SA_CBIT_R3: 7K3.8(V-)
7SA_CBIT_R4: 7K4.8(V-)
7SA_CBIT_R5: 7K5.8(V-)
7SA_CBIT_R6: 7K6.8(V-)
7SA_CBIT_R7: 7K7.8(V-)
7SA_CBIT_R29: 7K29.8(V-)
7SA_CBIT_R32: 7K32.8(V-)
7SA_CBIT_R34: 7K34.8(V-)
7SA_CBIT_S01: 7R163.1
7SA_CBIT_S02: 7R164.1
7SA_CBIT_S03: 7R165.1
7SA_CBIT_S25: 7MK1.2(V-) 7MR12.2
7SA_CBIT_S26: 7MK2.2(V-) 7MR15.2
7SA_CBIT_S27: 7MK4.2(V-) 7MR17.2
7SA_CBIT_S28: 7MK3.2(V-)
7SA_CBIT_S97: 7R982.1
S4_0V5: 4C286.1 4C288.1 4MK1.4 4MR2.2 4MR3.1 4MR4.1 4MR5.1 4MR6.1 4MU3.3(+IN)
S4_0V25: 4MK4.3 4MR18.2 4MR19.1
S4_0V75: 4C290.1 4MK2.4 4MR10.2 4MU3.6(OUT)
S4_1SPI_CK: 4K2.7
S4_1SPI_DI: 4K4.7
S4_1SPI_DO: 4K4.2
S4_1SPI_HLD: 4K6.2
S4_1SPI_WPZ: 4K6.7
S4_3V3_USB2_MUX: 4BD21.2 4C262.1 4U31.4(VCC)
S4_3V3_XTAL32K: 4BD1728.2 4C1074.1 4R981.1 4U449.10(VCC)
S4_AWG_3SHARE+: 4K34.4 ; also on sheet 20
S4_B_DCH105: SITE4.C12(PAD_RTC_IO4)
S4_B_DCH106: SITE4.D13(PAD_RTC_IO5)
S4_DCH015: SITE4.N1(PAD_AUD_MICCM0)
S4_DCH016: SITE4.L1(PAD_AUD_MICCM1)
S4_DCH017: SITE4.L3(PAD_AUD_LINEOUT_RP)
S4_DCH018: SITE4.L4(PAD_AUD_LINEOUT_RN)
S4_DCH063: SITE4.A17(PAD_PM_SDIO_CLK)
S4_DCH064: SITE4.B16(PAD_PM_SDIO_CMD)
S4_DCH065: SITE4.A18(PAD_PM_SDIO_D0)
S4_DCH066: SITE4.B18(PAD_PM_SDIO_D1)
S4_DCH067: SITE4.B15(PAD_PM_SDIO_D2)
S4_DCH068: SITE4.A15(PAD_PM_SDIO_D3)
S4_DCH069: SITE4.B19(PAD_PM_SDIO_INT)
S4_DCH082: SITE4.D15(PAD_PM_FUART_CTS)
S4_DCH083: SITE4.D16(PAD_PM_FUART_RTS)
S4_DCH088: SITE4.G20(PAD_PM_PWM2)
S4_DCH089: SITE4.H20(PAD_PM_PWM3)
S4_DCH090: SITE4.A21(PAD_PM_SAR_GPIO1)
S4_DCH103: SITE4.E12(PAD_RTC_IO0)
S4_DCH104: SITE4.D12(PAD_RTC_IO1)
S4_DCH107: SITE4.E11(PAD_RESET)
S4_DCH108: 4K32.2
S4_DCH109: 4K32.7
S4_DCH110: 4U449.3(MHL+)
S4_DCH111: 4U449.4(MHL-)
S4_M_2V5: 4C284.1 4C285.1 4MR2.1 4MU2.6(VOUT)
S4_M_3V2: 4C282.1 4C283.1 4C289.1 4MR1.1 4MU1.5(Vout) 4MU2.2(VIN) 4MU3.7(V+)
S4_Mpdch01: SITE4.D7(PAD_I2C1_SDA)
S4_Mpdch03+: 4U31.2(D+)
S4_Mpdch03-: 4U31.3(D-)
S4_Mpdch05: SITE4.E7(PAD_I2C1_SCL)
S4_Mpdch06: SITE4.T4(PAD_SD0_D1)
S4_Mpdch09: SITE4.E8(PAD_SR_RST0)
S4_Mpdch10: SITE4.D8(PAD_SR_MCLK0)
S4_Mpdch11: SITE4.T3(PAD_SD0_CDZ)
S4_Mpdch13: SITE4.U4(PAD_SD0_D0)
S4_Mpdch14: SITE4.U5(PAD_SD0_CLK)
S4_Mpdch15: SITE4.T6(PAD_SD0_CMD)
S4_Mpdch16: SITE4.U7(PAD_SD0_D3)
S4_Mpdch17: SITE4.T7(PAD_SD0_D2)
S4_Mpdch18: SITE4.U20(PAD_FUART_RX)
S4_Mpdch19: SITE4.U21(PAD_FUART_TX)
S4_Mpdch20: SITE4.U18(PAD_FUART_RTS)
S4_Mpdch21: SITE4.R2(PAD_GPIO0)
S4_Mpdch22: SITE4.P6(PAD_GPIO5)
S4_Mpdch23: SITE4.R3(PAD_GPIO1)
S4_Mpdch24: SITE4.T2(PAD_GPIO10)
S4_Mpdch25: SITE4.R1(PAD_GPIO8)
S4_Mpdch26: SITE4.T1(PAD_GPIO9)
S4_Mpdch27: SITE4.P7(PAD_GPIO6)
S4_Mpdch28: SITE4.P4(PAD_GPIO3)
S4_Mpdch29: SITE4.U2(PAD_GPIO11)
S4_Mpdch30: SITE4.R7(PAD_GPIO7)
S4_Mpdch32: 4K2.2
S4_Mpdch33: SITE4.L2(PAD_AUD_MICIN1)
S4_Mpdch34: 4C264.1 SITE4.M3(PAD_AUD_VAG)
S4_Mpdch35: SITE4.N2(PAD_AUD_MICIN0)
S4_Mpdch36: SITE4.L20(PAD_I2C0_SDA)
S4_Mpdch49: SITE4.E5(PAD_SR_RST1)
S4_Mpdch50: SITE4.D5(PAD_SR_MCLK1)
S4_Mpdch51: SITE4.T18(PAD_FUART_CTS)
S4_Mpdch52: SITE4.T19(PAD_MSPI0_CZ)
S4_Mpdch53: SITE4.R4(PAD_GPIO2)
S4_Mpdch54: SITE4.P5(PAD_GPIO4)
S4_Mpdch55: SITE4.D4(PAD_I2C2_SCL)
S4_Mpdch56: SITE4.E4(PAD_I2C2_SDA)
S4_Mpdch57: SITE4.N19(PAD_MSPI0_CK)
S4_Mpdch58: SITE4.P19(PAD_MSPI0_DI)
S4_Mpdch59: SITE4.R19(PAD_MSPI0_DO)
S4_Mpdch60: SITE4.M20(PAD_I2C0_SCL)
S4_Mpdch61: SITE4.G21(PAD_PM_UART_RX)
S4_Mpdch62: SITE4.H22(PAD_PM_UART_TX)
S4_Mpdch63: SITE4.C19(PAD_PM_I2C_SDA)
S4_Mpdch64: SITE4.D19(PAD_PM_I2C_SCL)
S4_Mpdch65: SITE4.B22(PAD_PM_GPIO5)
S4_Mpdch66: SITE4.C22(PAD_PM_GPIO6)
S4_Mpdch68: SITE4.B21(PAD_PM_GPIO4)
S4_Mpdch69: SITE4.F19(PAD_PM_PWM1)
S4_Mpdch71: SITE4.H21(PAD_PM_GPIO11)
S4_Mpdch72: SITE4.E15(PAD_PM_FUART_RX)
S4_Mpdch73: SITE4.E18(PAD_PM_GPIO2)
S4_Mpdch74: SITE4.D18(PAD_PM_GPIO3)
S4_Mpdch75: SITE4.E22(PAD_PM_PSPI0_DO)
S4_Mpdch76: SITE4.F22(PAD_PM_PSPI0_DI)
S4_Mpdch77: SITE4.E19(PAD_PM_PWM0)
S4_Mpdch78: SITE4.C20(PAD_PM_UART2_RX)
S4_Mpdch79: SITE4.D20(PAD_PM_UART2_TX)
S4_Mpdch80: SITE4.E21(PAD_PM_PSPI0_CK)
S4_Mpdch81: SITE4.D21(PAD_PM_PSPI0_CZ)
S4_Mpdch84: SITE4.F21(PAD_PM_PSPI0_INT)
S4_Mpdch85: SITE4.E17(PAD_PM_GPIO1)
S4_Mpdch86: SITE4.C16(PAD_PM_GPIO0)
S4_Mpdch87: SITE4.E14(PAD_PM_FUART_TX)
S4_Mpdch88: 4K34.2
S4_MUX_3V3: 4BD21.1 4BD1728.1 4R512.1 ; also on sheet 9
S4_PM_SAR_GPIO0: 4K34.3 4MK3.4 S4_VREF_OUT.1(TP) SITE4.A20(PAD_PM_SAR_GPIO0)
S4_SPI_CK_ABCD_CASE: 4K2.6 SITE4.T22(PAD_SPI_CK)
S4_SPI_CK_B_CASE: 4K2.5 4K3.6
S4_SPI_CK_C_CASE: 4K3.7 4U18.7(RESET#)
S4_SPI_CK_D_CASE: 4K3.5 4U19.6
S4_SPI_CZ_ABCD_CASE: 4K2.3 SITE4.M21(PAD_SPI_CZ)
S4_SPI_CZ_B_CASE: 4K2.4 4K3.3
S4_SPI_CZ_C_CASE: 4K3.2 4R200.2 4U18.1(CS#)
S4_SPI_CZ_D_CASE: 4K3.4 4R205.2 4U19.1
S4_SPI_DI_ABCD_CASE: 4K4.6 SITE4.R21(PAD_SPI_DI)
S4_SPI_DI_B_CASE: 4K4.5 4K5.6
S4_SPI_DI_C_CASE: 4K5.7
S4_SPI_DI_D_CASE: 4K5.5 4U19.5
S4_SPI_DO_ABCD_CASE: 4K4.3 SITE4.P22(PAD_SPI_DO)
S4_SPI_DO_B_CASE: 4K4.4 4K5.3
S4_SPI_DO_C_CASE: 4K5.2
S4_SPI_DO_D_CASE: 4K5.4 4U19.2
S4_SPI_HLD_ABCD_CASE: 4K6.3 SITE4.P21(PAD_SPI_HLD)
S4_SPI_HLD_B_CASE: 4K6.4 4K7.3
S4_SPI_HLD_C_CASE: 4K7.2 4R202.1
S4_SPI_HLD_D_CASE: 4K7.4 4R206.1 4U19.7
S4_SPI_WPZ_ABCD_CASE: 4K6.6 SITE4.N21(PAD_SPI_WPZ)
S4_SPI_WPZ_B_CASE: 4K6.5 4K7.6
S4_SPI_WPZ_C_CASE: 4K7.7 4R203.2 4U18.2(SO)
S4_SPI_WPZ_D_CASE: 4K7.5 4R207.2 4U19.3
S4_USB2_SEL0: 4R164.2 4U31.6(SEL0)
S4_USB2_SEL1: 4R163.2 4U31.5(SEL1)
S4_USB2_SELS: 4R165.2 4U31.16(SELS)
S4_USB_D_AB_CASE+: 4U31.10(HSD2+) SITE4.J3(PAD_DP_USB)
S4_USB_D_AB_CASE-: 4U31.9(HSD2-) SITE4.J2(PAD_DM_USB)
S4_USB_D_B_CASE+: 4R160.2 4U31.8(HSD2S+)
S4_USB_D_B_CASE-: 4R161.2 4U31.7(HSD2S-)
S4_USER_3V3: 4C334.1 4C335.1 4C336.2 4C337.2 4C338.2 4C339.2 4R200.1 4R201.2 4R202.2 4R203.1 4R204.2 4R205.1 4R206.2 4R207.1 4U17.3(Vout) S4_USER_3V3.1
S4_XTAL_24M_IN_ABC_CASE: 4K32.3 SITE4.L22(PAD_XTAL_IN_24M)
S4_XTAL_24M_IN_B_CASE: 4K32.4 4R135.1
S4_XTAL_24M_IN_C_CASE: 4C267.1 4R135.2 4R136.2 4Y1.3
S4_XTAL_24M_OUT_ABC_CASE: 4K32.6 SITE4.K21(PAD_XTAL_OUT_24M)
S4_XTAL_24M_OUT_B_CASE: 4K32.5 4R137.1
S4_XTAL_24M_OUT_C_CASE: 4C268.1 4R136.1 4R137.2 4Y1.1
S4_XTAL_IN_32K_A_CASE: 4K29.7 4U449.7(D-)
S4_XTAL_IN_32K_ABCD_CASE: 4K29.6 SITE4.B13(PAD_XTAL_IN_32K)
S4_XTAL_IN_32K_B_CASE: 4C271.1 4K29.5 4Y2.1
S4_XTAL_IN_32K_D_CASE: 4R923.1 4R973.2 4U449.2(USB-)
S4_XTAL_OUT_32K_A_CASE: 4K29.2 4U449.8(D+)
S4_XTAL_OUT_32K_ABCD_CASE: 4K29.3 SITE4.A12(PAD_XTAL_OUT_32K)
S4_XTAL_OUT_32K_B_CASE: 4C272.1 4K29.4 4Y2.2
S4_XTAL_OUT_32K_D_CASE: 4R652.1 4R973.1 4U449.1(USB+)
S7_0V5: 7C286.1 7C288.1 7MK1.4 7MR2.2 7MR3.1 7MR4.1 7MR5.1 7MR6.1 7MU3.3(+IN)
S7_0V25: 7MK4.3 7MR18.2 7MR19.1
S7_0V75: 7C290.1 7MK2.4 7MR10.2 7MU3.6(OUT)
S7_1SPI_CK: 7K2.7
S7_1SPI_DI: 7K4.7
S7_1SPI_DO: 7K4.2
S7_1SPI_HLD: 7K6.2
S7_1SPI_WPZ: 7K6.7
S7_3V3_USB2_MUX: 7BD21.2 7C262.1 7U31.4(VCC)
S7_3V3_XTAL32K: 7BD1728.2 7C1074.1 7R981.1 7U449.10(VCC)
S7_AWG_3SHARE+: 7K34.4 ; also on sheet 20
S7_B_DCH105: SITE7.C12(PAD_RTC_IO4)
S7_B_DCH106: SITE7.D13(PAD_RTC_IO5)
S7_DCH015: SITE7.N1(PAD_AUD_MICCM0)
S7_DCH016: SITE7.L1(PAD_AUD_MICCM1)
S7_DCH017: SITE7.L3(PAD_AUD_LINEOUT_RP)
S7_DCH018: SITE7.L4(PAD_AUD_LINEOUT_RN)
S7_DCH063: SITE7.A17(PAD_PM_SDIO_CLK)
S7_DCH064: SITE7.B16(PAD_PM_SDIO_CMD)
S7_DCH065: SITE7.A18(PAD_PM_SDIO_D0)
S7_DCH066: SITE7.B18(PAD_PM_SDIO_D1)
S7_DCH067: SITE7.B15(PAD_PM_SDIO_D2)
S7_DCH068: SITE7.A15(PAD_PM_SDIO_D3)
S7_DCH069: SITE7.B19(PAD_PM_SDIO_INT)
S7_DCH082: SITE7.D15(PAD_PM_FUART_CTS)
S7_DCH083: SITE7.D16(PAD_PM_FUART_RTS)
S7_DCH088: SITE7.G20(PAD_PM_PWM2)
S7_DCH089: SITE7.H20(PAD_PM_PWM3)
S7_DCH090: SITE7.A21(PAD_PM_SAR_GPIO1)
S7_DCH103: SITE7.E12(PAD_RTC_IO0)
S7_DCH104: SITE7.D12(PAD_RTC_IO1)
S7_DCH107: SITE7.E11(PAD_RESET)
S7_DCH108: 7K32.2
S7_DCH109: 7K32.7
S7_DCH110: 7U449.3(MHL+)
S7_DCH111: 7U449.4(MHL-)
S7_M_2V5: 7C284.1 7C285.1 7MR2.1 7MU2.6(VOUT)
S7_M_3V2: 7C282.1 7C283.1 7C289.1 7MR1.1 7MU1.5(Vout) 7MU2.2(VIN) 7MU3.7(V+)
S7_Mpdch01: SITE7.D7(PAD_I2C1_SDA)
S7_Mpdch03+: 7U31.2(D+)
S7_Mpdch03-: 7U31.3(D-)
S7_Mpdch05: SITE7.E7(PAD_I2C1_SCL)
S7_Mpdch06: SITE7.T4(PAD_SD0_D1)
S7_Mpdch09: SITE7.E8(PAD_SR_RST0)
S7_Mpdch10: SITE7.D8(PAD_SR_MCLK0)
S7_Mpdch11: SITE7.T3(PAD_SD0_CDZ)
S7_Mpdch13: SITE7.U4(PAD_SD0_D0)
S7_Mpdch14: SITE7.U5(PAD_SD0_CLK)
S7_Mpdch15: SITE7.T6(PAD_SD0_CMD)
S7_Mpdch16: SITE7.U7(PAD_SD0_D3)
S7_Mpdch17: SITE7.T7(PAD_SD0_D2)
S7_Mpdch18: SITE7.U20(PAD_FUART_RX)
S7_Mpdch19: SITE7.U21(PAD_FUART_TX)
S7_Mpdch20: SITE7.U18(PAD_FUART_RTS)
S7_Mpdch21: SITE7.R2(PAD_GPIO0)
S7_Mpdch22: SITE7.P6(PAD_GPIO5)
S7_Mpdch23: SITE7.R3(PAD_GPIO1)
S7_Mpdch24: SITE7.T2(PAD_GPIO10)
S7_Mpdch25: SITE7.R1(PAD_GPIO8)
S7_Mpdch26: SITE7.T1(PAD_GPIO9)
S7_Mpdch27: SITE7.P7(PAD_GPIO6)
S7_Mpdch28: SITE7.P4(PAD_GPIO3)
S7_Mpdch29: SITE7.U2(PAD_GPIO11)
S7_Mpdch30: SITE7.R7(PAD_GPIO7)
S7_Mpdch32: 7K2.2
S7_Mpdch33: SITE7.L2(PAD_AUD_MICIN1)
S7_Mpdch34: 7C264.1 SITE7.M3(PAD_AUD_VAG)
S7_Mpdch35: SITE7.N2(PAD_AUD_MICIN0)
S7_Mpdch36: SITE7.L20(PAD_I2C0_SDA)
S7_Mpdch49: SITE7.E5(PAD_SR_RST1)
S7_Mpdch50: SITE7.D5(PAD_SR_MCLK1)
S7_Mpdch51: SITE7.T18(PAD_FUART_CTS)
S7_Mpdch52: SITE7.T19(PAD_MSPI0_CZ)
S7_Mpdch53: SITE7.R4(PAD_GPIO2)
S7_Mpdch54: SITE7.P5(PAD_GPIO4)
S7_Mpdch55: SITE7.D4(PAD_I2C2_SCL)
S7_Mpdch56: SITE7.E4(PAD_I2C2_SDA)
S7_Mpdch57: SITE7.N19(PAD_MSPI0_CK)
S7_Mpdch58: SITE7.P19(PAD_MSPI0_DI)
S7_Mpdch59: SITE7.R19(PAD_MSPI0_DO)
S7_Mpdch60: SITE7.M20(PAD_I2C0_SCL)
S7_Mpdch61: SITE7.G21(PAD_PM_UART_RX)
S7_Mpdch62: SITE7.H22(PAD_PM_UART_TX)
S7_Mpdch63: SITE7.C19(PAD_PM_I2C_SDA)
S7_Mpdch64: SITE7.D19(PAD_PM_I2C_SCL)
S7_Mpdch65: SITE7.B22(PAD_PM_GPIO5)
S7_Mpdch66: SITE7.C22(PAD_PM_GPIO6)
S7_Mpdch68: SITE7.B21(PAD_PM_GPIO4)
S7_Mpdch69: SITE7.F19(PAD_PM_PWM1)
S7_Mpdch71: SITE7.H21(PAD_PM_GPIO11)
S7_Mpdch72: SITE7.E15(PAD_PM_FUART_RX)
S7_Mpdch73: SITE7.E18(PAD_PM_GPIO2)
S7_Mpdch74: SITE7.D18(PAD_PM_GPIO3)
S7_Mpdch75: SITE7.E22(PAD_PM_PSPI0_DO)
S7_Mpdch76: SITE7.F22(PAD_PM_PSPI0_DI)
S7_Mpdch77: SITE7.E19(PAD_PM_PWM0)
S7_Mpdch78: SITE7.C20(PAD_PM_UART2_RX)
S7_Mpdch79: SITE7.D20(PAD_PM_UART2_TX)
S7_Mpdch80: SITE7.E21(PAD_PM_PSPI0_CK)
S7_Mpdch81: SITE7.D21(PAD_PM_PSPI0_CZ)
S7_Mpdch84: SITE7.F21(PAD_PM_PSPI0_INT)
S7_Mpdch85: SITE7.E17(PAD_PM_GPIO1)
S7_Mpdch86: SITE7.C16(PAD_PM_GPIO0)
S7_Mpdch87: SITE7.E14(PAD_PM_FUART_TX)
S7_Mpdch88: 7K34.2
S7_MUX_3V3: 7BD21.1 7BD1728.1 7R512.1 ; also on sheet 3
S7_PM_SAR_GPIO0: 7K34.3 7MK3.4 S7_VREF_OUT.1(TP) SITE7.A20(PAD_PM_SAR_GPIO0)
S7_SPI_CK_ABCD_CASE: 7K2.6 SITE7.T22(PAD_SPI_CK)
S7_SPI_CK_B_CASE: 7K2.5 7K3.6
S7_SPI_CK_C_CASE: 7K3.7 7U18.7(RESET#)
S7_SPI_CK_D_CASE: 7K3.5 7U19.6
S7_SPI_CZ_ABCD_CASE: 7K2.3 SITE7.M21(PAD_SPI_CZ)
S7_SPI_CZ_B_CASE: 7K2.4 7K3.3
S7_SPI_CZ_C_CASE: 7K3.2 7R200.2 7U18.1(CS#)
S7_SPI_CZ_D_CASE: 7K3.4 7R205.2 7U19.1
S7_SPI_DI_ABCD_CASE: 7K4.6 SITE7.R21(PAD_SPI_DI)
S7_SPI_DI_B_CASE: 7K4.5 7K5.6
S7_SPI_DI_C_CASE: 7K5.7
S7_SPI_DI_D_CASE: 7K5.5 7U19.5
S7_SPI_DO_ABCD_CASE: 7K4.3 SITE7.P22(PAD_SPI_DO)
S7_SPI_DO_B_CASE: 7K4.4 7K5.3
S7_SPI_DO_C_CASE: 7K5.2
S7_SPI_DO_D_CASE: 7K5.4 7U19.2
S7_SPI_HLD_ABCD_CASE: 7K6.3 SITE7.P21(PAD_SPI_HLD)
S7_SPI_HLD_B_CASE: 7K6.4 7K7.3
S7_SPI_HLD_C_CASE: 7K7.2 7R202.1
S7_SPI_HLD_D_CASE: 7K7.4 7R206.1 7U19.7
S7_SPI_WPZ_ABCD_CASE: 7K6.6 SITE7.N21(PAD_SPI_WPZ)
S7_SPI_WPZ_B_CASE: 7K6.5 7K7.6
S7_SPI_WPZ_C_CASE: 7K7.7 7R203.2 7U18.2(SO)
S7_SPI_WPZ_D_CASE: 7K7.5 7R207.2 7U19.3
S7_USB2_SEL0: 7R164.2 7U31.6(SEL0)
S7_USB2_SEL1: 7R163.2 7U31.5(SEL1)
S7_USB2_SELS: 7R165.2 7U31.16(SELS)
S7_USB_D_AB_CASE+: 7U31.10(HSD2+) SITE7.J3(PAD_DP_USB)
S7_USB_D_AB_CASE-: 7U31.9(HSD2-) SITE7.J2(PAD_DM_USB)
S7_USB_D_B_CASE+: 7R160.2 7U31.8(HSD2S+)
S7_USB_D_B_CASE-: 7R161.2 7U31.7(HSD2S-)
S7_USER_3V3: 7C334.1 7C335.1 7C336.2 7C337.2 7C338.2 7C339.2 7R200.1 7R201.2 7R202.2 7R203.1 7R204.2 7R205.1 7R206.2 7R207.1 7U17.3(Vout) S7_USER_3V3.1
S7_XTAL_24M_IN_ABC_CASE: 7K32.3 SITE7.L22(PAD_XTAL_IN_24M)
S7_XTAL_24M_IN_B_CASE: 7K32.4 7R135.1
S7_XTAL_24M_IN_C_CASE: 7C267.1 7R135.2 7R136.2 7Y1.3
S7_XTAL_24M_OUT_ABC_CASE: 7K32.6 SITE7.K21(PAD_XTAL_OUT_24M)
S7_XTAL_24M_OUT_B_CASE: 7K32.5 7R137.1
S7_XTAL_24M_OUT_C_CASE: 7C268.1 7R136.1 7R137.2 7Y1.1
S7_XTAL_IN_32K_A_CASE: 7K29.7 7U449.7(D-)
S7_XTAL_IN_32K_ABCD_CASE: 7K29.6 SITE7.B13(PAD_XTAL_IN_32K)
S7_XTAL_IN_32K_B_CASE: 7C271.1 7K29.5 7Y2.1
S7_XTAL_IN_32K_D_CASE: 7R923.1 7R973.2 7U449.2(USB-)
S7_XTAL_OUT_32K_A_CASE: 7K29.2 7U449.8(D+)
S7_XTAL_OUT_32K_ABCD_CASE: 7K29.3 SITE7.A12(PAD_XTAL_OUT_32K)
S7_XTAL_OUT_32K_B_CASE: 7C272.1 7K29.4 7Y2.2
S7_XTAL_OUT_32K_D_CASE: 7R652.1 7R973.1 7U449.1(USB+)
UT1_UP5V: 4C278.1 4C279.1 4C280.1 4C281.1 4C332.1 4C333.1 4C476.1 4C477.1 4C478.1 4K2.1(V+) 4K3.1(V+) 4K4.1(V+) 4K5.1(V+) 4K6.1(V+) 4K7.1(V+) 4K29.1(V+) 4K32.1(V+) 4K34.1(V+) 4MBD1.1 4MR11.1 4MR12.1 4MR13.1 4MR14.2 4MR15.1 4MR16.1 4MR17.1 4MU1.1(Vin) 4MU1.3(EN) 4R331.1 4R509.2 4U17.2(Vin) 4U108.4(VDD) 7C278.1 7C279.1 7C280.1 7C281.1 7C332.1 7C333.1 7C476.1 7C477.1 7C478.1 7K2.1(V+) 7K3.1(V+) 7K4.1(V+) 7K5.1(V+) 7K6.1(V+) 7K7.1(V+) 7K29.1(V+) 7K32.1(V+) 7K34.1(V+) 7MBD1.1 7MR11.1 7MR12.1 7MR13.1 7MR14.2 7MR15.1 7MR16.1 7MR17.1 7MU1.1(Vin) 7MU1.3(EN) 7R331.1 7R509.2 7U17.2(Vin) 7U108.4(VDD) ; also on sheet 2 4 6 8 10 12 14 17 19 20 21 22 23 24 25 26 27 28 30 31 32 33 36 37
N22574128: 4R162.1 4U31.15(OE#)
N22574153: 4R510.2 4R511.1 4U108.1(ADJ)
N22574159: 4C475.1 4R510.1 4R512.2 4TP_MUX_3V3.1(TP) 4U108.5(VOUT)
N22574160: 4R509.1 4U108.3(CE)
N22574456: 4BD9.1 SITE4.N3(PAD_AUD_VRM)
N22574460: 4MU4.3(EN) 4R331.2
N22574494: 4C299.2 4MU4.1(FILTER)
N22574495: 4C300.1 4C301.1 4MR18.1 4MU4.5(OUTS) 4MU4.6(OUTF)
N22574500: 4C298.2 4MBD1.2 4MU4.4(IN)
N22574529: 4MR1.2 4MR7.2 4MU1.4(FB)
N22574539: 4MR8.1 4MR9.1 4MU3.2(-IN)
N22574576: 4MK2.1(V+) 4MR13.2
N22574581: 4MK1.3 4MK2.3 4MK3.3 4MK4.4
N22574588: 4MK3.1(V+) 4MR14.1
N22574592: 4MK4.1(V+) 4MR16.2
N22574613: 4MR9.2 4MR10.1
N22574614: 4MK1.1(V+) 4MR11.2
N22574782: 4R980.1 4U449.6(OE#)
N22574793: 4R981.2 4R982.2 4U449.9(SEL)
N22574915: 4R204.1 4U19.8
N22574935: 4R201.1 4U18.8(VCC)
N22597714: 7R162.1 7U31.15(OE#)
N22597739: 7R510.2 7R511.1 7U108.1(ADJ)
N22597745: 7C475.1 7R510.1 7R512.2 7TP_MUX_3V3.1(TP) 7U108.5(VOUT)
N22597746: 7R509.1 7U108.3(CE)
N22598042: 7BD9.1 SITE7.N3(PAD_AUD_VRM)
N22598046: 7MU4.3(EN) 7R331.2
N22598080: 7C299.2 7MU4.1(FILTER)
N22598081: 7C300.1 7C301.1 7MR18.1 7MU4.5(OUTS) 7MU4.6(OUTF)
N22598086: 7C298.2 7MBD1.2 7MU4.4(IN)
N22598115: 7MR1.2 7MR7.2 7MU1.4(FB)
N22598125: 7MR8.1 7MR9.1 7MU3.2(-IN)
N22598162: 7MK2.1(V+) 7MR13.2
N22598167: 7MK1.3 7MK2.3 7MK3.3 7MK4.4
N22598174: 7MK3.1(V+) 7MR14.1
N22598178: 7MK4.1(V+) 7MR16.2
N22598199: 7MR9.2 7MR10.1
N22598200: 7MK1.1(V+) 7MR11.2
N22598368: 7R980.1 7U449.6(OE#)
N22598379: 7R981.2 7R982.2 7U449.9(SEL)
N22598501: 7R204.1 7U19.8
N22598521: 7R201.1 7U18.8(VCC)

Not connected (* = marked no-connect by the designer): 4K34 5* 6* 7*; 4MU2 1(NC1)* 3(NC2)* 5(NC3)* 7(NC4)* 8(TP)*; 4MU3 1(NC1)* 5(NC2)* 8(NC3)*; 4U18 3(WP#) 4(GND) 5(SI) 6(SCLK); 4U19 GH1* GH2*; 4U31 11(HSD1+)* 12(HSD1-)* 13(HSD0+)* 14(HSD0-)*; 7K34 5* 6* 7*; 7MU2 1(NC1)* 3(NC2)* 5(NC3)* 7(NC4)* 8(TP)*; 7MU3 1(NC1)* 5(NC2)* 8(NC3)*; 7U18 3(WP#) 4(GND) 5(SI) 6(SCLK); 7U19 GH1* GH2*; 7U31 11(HSD1+)* 12(HSD1-)* 13(HSD0+)* 14(HSD0-)*; SITE4 A1(NC[0])* A3(NC[1])* A5(NC[2])* A7(NC[3])* A9(NC[4])* A11(NC[5])* A13(NC[6])* A14(NC[7])* A16(NC[8])* A19(NC[9])* A22(NC[10])* C5(NC[11])* C7(NC[12])* C9(NC[13])* C13(NC[14])* C18(NC[15])* C21(NC[16])* D1(NC[17])* D6(NC[18])* D9(NC[19])* D10(NC[20])* D11(NC[21])* D14(NC[22])* D17(NC[23])* D22(NC[24])* E6(NC[25])* E9(NC[26])* E13(NC[27])* E16(NC[28])* F1(NC[29])* F5(NC[30])* F11(NC[31])* F14(NC[32])* F16(NC[33])* F18(NC[34])* F20(NC[35])* G4(NC[36])* G19(NC[37])* G22(NC[38])* H1(NC[39])* H3(NC[40])* H5(NC[41])* H18(NC[42])* J1(NC[43])* J4(NC[44])* J19(NC[45])* J22(NC[46])* K1(NC[47])* K2(NC[48])* K3(NC[49])* K5(NC[50])* K18(NC[51])* K20(NC[52])* K22(NC[53])* L19(NC[54])* M1(NC[55])* M5(NC[56])* M19(NC[57])* M22(NC[58])* N4(NC[59])* N5(NC[60])* N18(NC[61])* N22(NC[62])* NGH1* NGH2* NGH3* NGH4* NUT1* NUT2* NUT3* NUT4* P1(NC[63])* P20(NC[64])* R5(NC[65])* R6(NC[66])* R10(NC[67])* R12(NC[68])* R13(NC[69])* R20(NC[70])* R22(NC[71])* T12(NC[72])* T20(NC[73])* U1(NC[74])* U3(NC[75])* U6(NC[76])* U8(NC[77])* U10(NC[78])* U12(NC[79])* U14(NC[80])* U17(NC[81])* U19(NC[82])* U22(NC[83])*; SITE7 A1(NC[0])* A3(NC[1])* A5(NC[2])* A7(NC[3])* A9(NC[4])* A11(NC[5])* A13(NC[6])* A14(NC[7])* A16(NC[8])* A19(NC[9])* A22(NC[10])* C5(NC[11])* C7(NC[12])* C9(NC[13])* C13(NC[14])* C18(NC[15])* C21(NC[16])* D1(NC[17])* D6(NC[18])* D9(NC[19])* D10(NC[20])* D11(NC[21])* D14(NC[22])* D17(NC[23])* D22(NC[24])* E6(NC[25])* E9(NC[26])* E13(NC[27])* E16(NC[28])* F1(NC[29])* F5(NC[30])* F11(NC[31])* F14(NC[32])* F16(NC[33])* F18(NC[34])* F20(NC[35])* G4(NC[36])* G19(NC[37])* G22(NC[38])* H1(NC[39])* H3(NC[40])* H5(NC[41])* H18(NC[42])* J1(NC[43])* J4(NC[44])* J19(NC[45])* J22(NC[46])* K1(NC[47])* K2(NC[48])* K3(NC[49])* K5(NC[50])* K18(NC[51])* K20(NC[52])* K22(NC[53])* L19(NC[54])* M1(NC[55])* M5(NC[56])* M19(NC[57])* M22(NC[58])* N4(NC[59])* N5(NC[60])* N18(NC[61])* N22(NC[62])* NGH1* NGH2* NGH3* NGH4* NUT1* NUT2* NUT3* NUT4* P1(NC[63])* P20(NC[64])* R5(NC[65])* R6(NC[66])* R10(NC[67])* R12(NC[68])* R13(NC[69])* R20(NC[70])* R22(NC[71])* T12(NC[72])* T20(NC[73])* U1(NC[74])* U3(NC[75])* U6(NC[76])* U8(NC[77])* U10(NC[78])* U12(NC[79])* U14(NC[80])* U17(NC[81])* U19(NC[82])* U22(NC[83])*

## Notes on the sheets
sheet 34
- USB 2.0
- Close to DUT
- USB¡BAUD
- DIFF 90 ohm
- 3.3V
- XTAL
- PAD_RTC_IO4~5: Use wider traces.
- XTAL_24M
- USB DC MUX:
- Close to DUT
- FSUSB73UMX-UMLP16
  RON (Typical): 6.5 £[
- SEL1
- SEL0
- Function
- (mUbit7)
- (mUbit8)
- 0
- 1
- NA
- 1
- 0
- NA
- 1
- 1
- USB DC(default)
- Trace Width: 20 mil
- Close to DUT
- SELS
- Function
- XTAL_32K
- (mUbit9)
- 1
- R_ON(default)
- Close to DUT
- 0
- R_OFF
- Close to DUT
- Connect the bead directly to GND.
- apply GND shielding.
- PAD_PM_GPIO3~5: Use wider traces
- GND
- SPI FLASH
- FLASH
- NOR
- NAND
- CS#
- VCC
- 8
- DO/IO1
- HOLD#/RST#IO3
- WP#/IO2
- SCLK
- GND
- DI/IO0
- 4
- 5
- NOR¡GW25Q128JVSIQ-SOIC8
  NAND¡GW25N01GVZEIG
- Please measure the output voltage before shipment.
  (1)0.25V +/-1% (0.2475~0.2525V)
  (2)0.5V +/-1% (0.495~0.505V)
  (3)0.75V +/-1% (0.7425~0.7575V)
- SAR_GPIO0: Precise voltage levels of 0.25 V / 0.5 V / 0.75 V.
- Vout=0.5*(1+499/1K)=0.7495V
- NO
- NO
- NC
- supply current 0.235mA
- VOUT = 3 V (fixed by part number). Max. output current: ¡Ó10 mA.
- High-precision 0.25 V reference voltage source (V0 = 3 V ¡Ñ [1K / 12K] = 0.25 V).
- Relay (CH, AWG, SAR_GPIO0): Provide precision voltage levels of 0.25 V / 0.5 V / 0.75 V.
- Connect the precision voltage source before the relay.
- MCB Assign: Only channels A¡VD are allowed.
  Channels can be interchanged.
- AWG
- Use copper shapes for all connections from DUT to MK3.
  Ensure consistency across all SITES.
- Relay~ AWG Apply GND shielding.
sheet 35
- USB 2.0
- Close to DUT
- USB¡BAUD
- DIFF 90 ohm
- 3.3V
- XTAL
- PAD_RTC_IO4~5: Use wider traces.
- XTAL_24M
- USB DC MUX:
- Close to DUT
- FSUSB73UMX-UMLP16
  RON (Typical): 6.5 £[
- SEL1
- SEL0
- Function
- (mUbit7)
- (mUbit8)
- 0
- 1
- NA
- 1
- 0
- NA
- 1
- 1
- USB DC(default)
- Trace Width: 20 mil
- Close to DUT
- SELS
- Function
- XTAL_32K
- (mUbit9)
- 1
- R_ON(default)
- Close to DUT
- 0
- R_OFF
- Close to DUT
- Connect the bead directly to GND.
- apply GND shielding.
- PAD_PM_GPIO3~5: Use wider traces
- GND
- SPI FLASH
- FLASH
- NOR
- NAND
- CS#
- VCC
- 8
- DO/IO1
- HOLD#/RST#IO3
- WP#/IO2
- SCLK
- GND
- DI/IO0
- 4
- 5
- NOR¡GW25Q128JVSIQ-SOIC8
  NAND¡GW25N01GVZEIG
- Please measure the output voltage before shipment.
  (1)0.25V +/-1% (0.2475~0.2525V)
  (2)0.5V +/-1% (0.495~0.505V)
  (3)0.75V +/-1% (0.7425~0.7575V)
- SAR_GPIO0: Precise voltage levels of 0.25 V / 0.5 V / 0.75 V.
- Vout=0.5*(1+499/1K)=0.7495V
- NO
- NO
- NC
- supply current 0.235mA
- VOUT = 3 V (fixed by part number). Max. output current: ¡Ó10 mA.
- High-precision 0.25 V reference voltage source (V0 = 3 V ¡Ñ [1K / 12K] = 0.25 V).
- Relay (CH, AWG, SAR_GPIO0): Provide precision voltage levels of 0.25 V / 0.5 V / 0.75 V.
- Connect the precision voltage source before the relay.
- MCB Assign: Only channels A¡VD are allowed.
  Channels can be interchanged.
- AWG
- Use copper shapes for all connections from DUT to MK3.
  Ensure consistency across all SITES.
- Relay~ AWG Apply GND shielding.
